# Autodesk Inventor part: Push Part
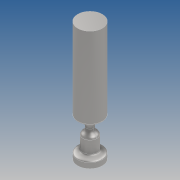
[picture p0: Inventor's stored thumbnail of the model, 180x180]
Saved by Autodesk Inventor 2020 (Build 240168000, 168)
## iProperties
Created: 2019-10
Part Number: Push Part
Material: Generic
Document SubType Name: Modeling
Designer: yello
Density: 1 g/cm^3
Appearance: Default
Author: yello
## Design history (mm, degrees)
sketch "Sketch2" dims "d4" = 3
  geometry: L1 (0, 0)-(2, 0); L2 (0, 0)-(0, -26); L3 (0, -26)-(2.5, -26); L4 (2.5, -26)-(2.5, -24); L5 (2.5, -24)-(3.5, -24); L6 (0, -26)-(0, -28); L7 (0, -28)-(2, -28); L8 (2, -24)-(2, 0); L9 (0, -28)-(0, -32.5); L10 (2, -28)-(2, -30); L11 (0, -32.5)-(2, -32.5); L12 (2, -32.5)-(2, -30); L13 (2, -28)-(2, -27.177); L14 (2, -27.177)-(1, -27.177); L15 (1, -27.177)-(1, -26); L16 (2, -24)-(2, -24.823); L17 (2, -24.823)-(1, -24.823); L18 (1, -24.823)-(1, -26); L19 (2, -31.5)-(2, -34); L20 (3.5, -32.5)-(3.5, -34); L21 (3.5, -34)-(2, -34); L22 (2, -34)-(0, -34); L23 (0, -34)-(0, -32.5); L24 (2, -31.5)-(2, -32.5); L25 (2, -31.5)-(2, -32); L26 (2, -32)-(3.5, -32); L27 (3.5, -32)-(3.5, -32.5); L28 (2, -24)-(2, -23); L29 (2, 0)-(3.5, 0); L30 (3.5, 0)-(3.5, -23.002); L31 (2, -24)-(2, -23.5); L32 (2, -23.5)-(3.5, -23.501); L33 (3.5, -23.501)-(3.5, -23.002)
  constraints: 42 end point, 9 perpendicular, 6 point on line, 6 vertical, 5 horizontal, 3 symmetric about line, 2 midpoint, 1 coincident, 1 horizontal alignment, 14 other
  dimensions: "d0" = 2 distance of L1.start L1.end; "d2" = 26 distance of L1.start L2.end; "d7" = 2 distance of L4.start L4.end; "d8" = 1.5 distance of L5.end L8.start; "d9" = 4.5 distance of L6.end L9.end; "d10" = 2 distance of L7.end L10.end; "d11" = 2.5 distance of L2.end L3.end; "d13" = 2.5 distance of L19.start L19.end; "d15" = 1 distance of L8.start L28.end; "d16" = 1.5 distance of L1.end L29.end
revolve "Revolution1" sketch "Sketch2" stored, may be unused: angle "d17" = 90 deg
body "Solid1"
